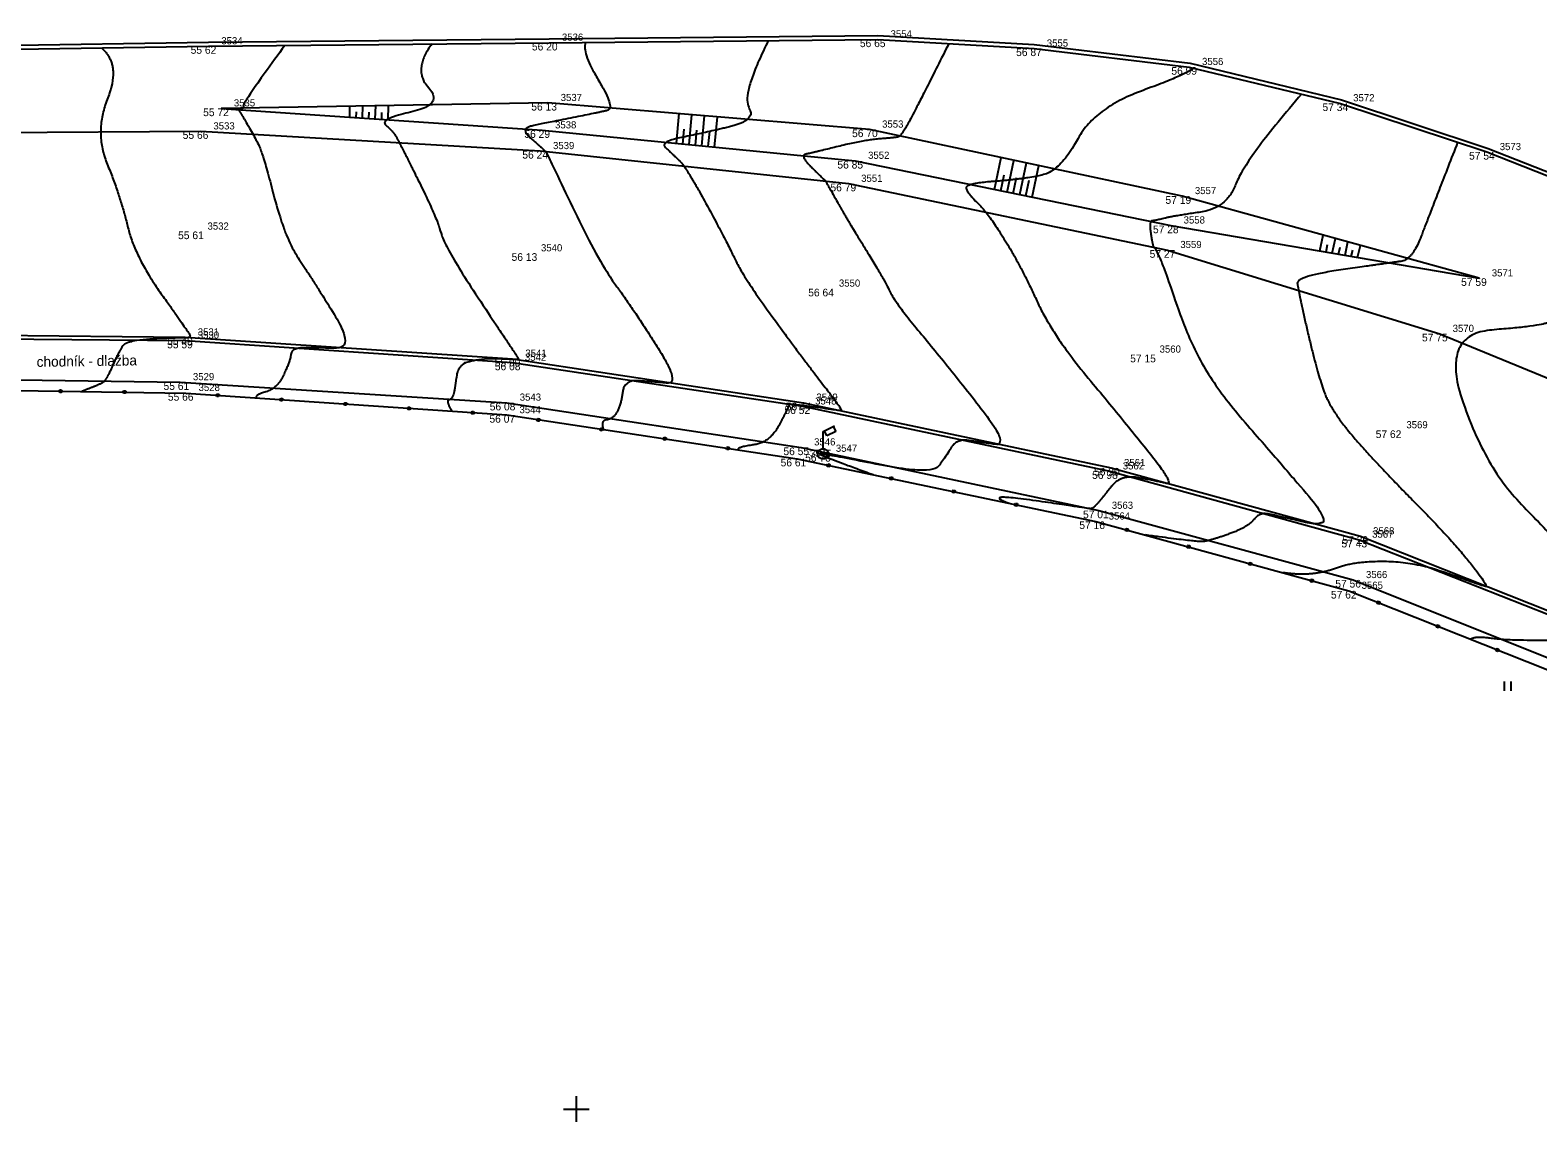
# Model space of a CAD drawing. Extents: x -704017 to -701500, y -1008977 to -1008450.
# Drawn here: x -702071.4 to -702012.4, y -1008850.5 to -1008807.8 of the extents above; entities that cross this region are included whole.
import ezdxf

# ---------------------------------------------------------------- set-up
doc = ezdxf.new("R2010")
doc.units = 0
for name, color, linetype in [('Z_body', 7, 'Continuous'), ('Z_body_cisla', 7, 'Continuous'), ('Z_body_vysky', 7, 'Continuous'), ('Z_chodnik', 7, 'Continuous'), ('Z_hekt_sit', 7, 'Continuous'), ('Z_komunikace', 7, 'Continuous'), ('Z_obruby', 7, 'Continuous'), ('Z_oploceni', 7, 'Continuous'), ('Z_popis', 7, 'Continuous'), ('Z_site_znaky_VO', 7, 'Continuous'), ('Z_teren_hrany_paty', 7, 'Continuous'), ('Z_vrstevnice_hlavni', 7, 'Continuous'), ('Z_vrstevnice_vedlejsi', 7, 'Continuous'), ('Z_zabradli', 7, 'Continuous')]:
    doc.layers.add(name, color=color, linetype=linetype)

# ---------------------------------------------------------------- blocks, each defined once
blk = doc.blocks.new('POINT_DISPLAY')
blk.add_line((0, 0), (0, 0))
blk = doc.blocks.new('Z530')
for p, q in [((-0.05, 0.03), (-0.03, 0.05)), ((-0.05, -0.03), (-0.05, 0.03)), ((-0.03, 0.05), (0.03, 0.05)), ((-0.03, -0.03), (-0.03, 0.03)), ((-0.03, 0.03), (0.03, 0.03)), ((-0.03, -0.03), (0.03, 0.03)), ((0.03, 0.05), (0.05, 0.03)), ((0.03, 0.03), (0.03, -0.03)), ((0.05, 0.03), (0.05, -0.03)), ((-0.03, -0.05), (-0.05, -0.03)), ((0.03, -0.03), (-0.03, -0.03)), ((0.03, -0.05), (-0.03, -0.05)), ((0.05, -0.03), (0.03, -0.05))]:
    blk.add_line(p, q)
blk = doc.blocks.new('Z306')
for p, q in [((-0.13, 0.17), (-0.13, -0.2)), ((0.13, 0.17), (0.13, -0.2))]:
    blk.add_line(p, q)
blk = doc.blocks.new('Z13')
for p, q in [((0, 0.88), (0.45, 1.1)), ((0, 0.2), (0, 0.88)), ((0.15, 0.7), (0.05, 0.9)), ((0.5, 0.88), (0.15, 0.7)), ((0.4, 1.07), (0.5, 0.88)), ((-0.2, 0.05), (-0.15, 0.15)), ((-0.2, -0.05), (-0.2, 0.05)), ((-0.15, 0.15), (-0.05, 0.2)), ((-0.05, 0.2), (0.05, 0.2)), ((0.05, 0.2), (0.15, 0.15)), ((0.15, 0.15), (0.2, 0.05)), ((0.2, 0.05), (0.2, -0.05)), ((-0.15, -0.15), (-0.2, -0.05)), ((-0.05, -0.2), (-0.15, -0.15)), ((0.05, -0.2), (-0.05, -0.2)), ((0.15, -0.15), (0.05, -0.2)), ((0.2, -0.05), (0.15, -0.15))]:
    blk.add_line(p, q)

msp = doc.modelspace()

# ---------------------------------------------------------------- linework, layer by layer
at = {"layer": 'Z_chodnik'}
for p, q in [((-702073.95, -1008821.44), (-702065.49, -1008821.57)), ((-702065.49, -1008821.57), (-702052.71, -1008822.37)), ((-702052.71, -1008822.37), (-702041.2, -1008824.12)), ((-702041.2, -1008824.12), (-702029.56, -1008826.59)), ((-702029.56, -1008826.59), (-702019.62, -1008829.3)), ((-702019.62, -1008829.3), (-702008.73, -1008833.67))]:
    msp.add_line(p, q, dxfattribs=at)
at = {"layer": 'Z_hekt_sit'}
for p, q in [((-702050, -1008849.5), (-702050, -1008850.5)), ((-702050.5, -1008850), (-702049.5, -1008850))]:
    msp.add_line(p, q, dxfattribs=at)
at = {"layer": 'Z_komunikace'}
for p, q in [((-702080.32, -1008811.84), (-702064.69, -1008811.75)), ((-702064.69, -1008811.75), (-702051.41, -1008812.52)), ((-702051.41, -1008812.52), (-702039.36, -1008813.8)), ((-702039.36, -1008813.8), (-702026.88, -1008816.4)), ((-702026.88, -1008816.4), (-702016.23, -1008819.67)), ((-702074.49, -1008819.71), (-702065.3, -1008819.81)), ((-702065.3, -1008819.81), (-702052.49, -1008820.65)), ((-702016.23, -1008819.67), (-702005.37, -1008824.15)), ((-702052.49, -1008820.65), (-702041.11, -1008822.37)), ((-702041.11, -1008822.37), (-702029.08, -1008824.92)), ((-702029.08, -1008824.92), (-702019.34, -1008827.59)), ((-702019.34, -1008827.59), (-702008.04, -1008832.07))]:
    msp.add_line(p, q, dxfattribs=at)
at = {"layer": 'Z_obruby'}
for p, q in [((-702074.45, -1008819.86), (-702065.3, -1008819.94)), ((-702065.3, -1008819.94), (-702052.51, -1008820.8)), ((-702052.51, -1008820.8), (-702041.16, -1008822.51)), ((-702041.16, -1008822.51), (-702029.13, -1008825.05)), ((-702029.13, -1008825.05), (-702019.38, -1008827.73)), ((-702019.38, -1008827.73), (-702008.12, -1008832.18))]:
    msp.add_line(p, q, dxfattribs=at)
at = {"layer": 'Z_oploceni'}
for p, q in [((-702080.8, -1008808.52), (-702064.38, -1008808.27)), ((-702064.38, -1008808.27), (-702051.06, -1008808.14)), ((-702064.38, -1008808.42), (-702051.06, -1008808.29)), ((-702051.06, -1008808.14), (-702038.21, -1008808.01)), ((-702051.06, -1008808.29), (-702038.21, -1008808.16)), ((-702038.21, -1008808.01), (-702032.09, -1008808.36)), ((-702038.21, -1008808.16), (-702032.1, -1008808.51)), ((-702080.8, -1008808.67), (-702064.38, -1008808.42)), ((-702032.1, -1008808.51), (-702026.03, -1008809.24)), ((-702032.09, -1008808.36), (-702026, -1008809.09)), ((-702026.03, -1008809.24), (-702020.12, -1008810.66)), ((-702026, -1008809.09), (-702020.08, -1008810.52)), ((-702020.12, -1008810.66), (-702014.39, -1008812.56)), ((-702020.08, -1008810.52), (-702014.34, -1008812.42)), ((-702014.34, -1008812.42), (-702010.8, -1008813.82)), ((-702014.39, -1008812.56), (-702010.86, -1008813.96))]:
    msp.add_line(p, q, dxfattribs=at)
at = {"layer": 'Z_teren_hrany_paty'}
for p, q in [((-702051.11, -1008810.64), (-702063.89, -1008810.86)), ((-702038.54, -1008811.68), (-702051.11, -1008810.64)), ((-702063.89, -1008810.86), (-702051.33, -1008811.71)), ((-702058.86, -1008811.2), (-702058.85, -1008810.77)), ((-702058.61, -1008811.22), (-702058.6, -1008810.99)), ((-702058.36, -1008811.23), (-702058.34, -1008810.76)), ((-702058.11, -1008811.25), (-702058.1, -1008811.01)), ((-702057.86, -1008811.27), (-702057.84, -1008810.76)), ((-702057.61, -1008811.29), (-702057.6, -1008811.02)), ((-702057.36, -1008811.3), (-702057.34, -1008810.75)), ((-702046.08, -1008812.22), (-702045.98, -1008811.06)), ((-702045.58, -1008812.27), (-702045.48, -1008811.11)), ((-702045.09, -1008812.32), (-702044.98, -1008811.15)), ((-702044.59, -1008812.37), (-702044.48, -1008811.19)), ((-702051.33, -1008811.71), (-702039.09, -1008812.91)), ((-702045.83, -1008812.25), (-702045.78, -1008811.67)), ((-702045.34, -1008812.3), (-702045.28, -1008811.71)), ((-702044.84, -1008812.35), (-702044.78, -1008811.76)), ((-702026.31, -1008814.29), (-702038.54, -1008811.68)), ((-702039.09, -1008812.91), (-702026.75, -1008815.44)), ((-702033.64, -1008814.03), (-702033.38, -1008812.78)), ((-702033.15, -1008814.13), (-702032.89, -1008812.89)), ((-702032.66, -1008814.23), (-702032.4, -1008812.99)), ((-702033.4, -1008814.08), (-702033.27, -1008813.46)), ((-702032.91, -1008814.18), (-702032.78, -1008813.56)), ((-702032.17, -1008814.33), (-702031.91, -1008813.09)), ((-702032.42, -1008814.28), (-702032.29, -1008813.66)), ((-702014.7, -1008817.5), (-702026.31, -1008814.29)), ((-702026.75, -1008815.44), (-702014.7, -1008817.5)), ((-702020.93, -1008816.43), (-702020.79, -1008815.82)), ((-702020.44, -1008816.52), (-702020.31, -1008815.95)), ((-702020.68, -1008816.48), (-702020.62, -1008816.18)), ((-702020.19, -1008816.56), (-702020.13, -1008816.29)), ((-702019.94, -1008816.6), (-702019.83, -1008816.08)), ((-702019.7, -1008816.65), (-702019.64, -1008816.4)), ((-702019.45, -1008816.69), (-702019.34, -1008816.22))]:
    msp.add_line(p, q, dxfattribs=at)
at = {"layer": 'Z_vrstevnice_hlavni'}
for points in [[(-702055.653, -1008808.335), (-702056.406, -1008809.361), (-702055.162, -1008810.71), (-702057.72, -1008811.278), (-702057.17, -1008811.754), (-702056.905, -1008812.201), (-702055.423, -1008815.201), (-702055.14, -1008816.307), (-702052.446, -1008820.355), (-702052.237, -1008820.688), (-702052.276, -1008820.685), (-702052.492, -1008820.667), (-702054.598, -1008820.66), (-702054.766, -1008821.973), (-702054.885, -1008822.234), (-702055.102, -1008822.298), (-702054.863, -1008822.703)], [(-702025.861, -1008809.281), (-702026.044, -1008809.493), (-702029.748, -1008810.858), (-702031.052, -1008813.278), (-702032.442, -1008813.625), (-702034.785, -1008813.793), (-702034.729, -1008814.156), (-702033.9, -1008814.938), (-702032.601, -1008817.047), (-702031.378, -1008819.731), (-702028.524, -1008823.148), (-702026.583, -1008825.605), (-702027.25, -1008825.45), (-702028.697, -1008825.169), (-702029.417, -1008826.077), (-702029.813, -1008826.536), (-702030.029, -1008826.493), (-702034.173, -1008825.898), (-702033.078, -1008826.297)]]:
    msp.add_open_spline(points, degree=2, dxfattribs=at)
at = {"layer": 'Z_vrstevnice_vedlejsi'}
for points in [[(-702049.632, -1008808.276), (-702049.808, -1008808.629), (-702048.464, -1008810.859), (-702049.107, -1008811.018), (-702051.275, -1008811.443), (-702052.211, -1008811.65), (-702051.394, -1008812.358), (-702051.191, -1008812.543), (-702051.131, -1008812.655), (-702049.139, -1008816.847), (-702047.711, -1008818.785), (-702045.915, -1008821.644), (-702046.932, -1008821.562), (-702048.125, -1008821.461), (-702048.248, -1008822.424), (-702048.547, -1008823.003), (-702049.069, -1008823.072), (-702048.933, -1008823.42)], [(-702042.493, -1008808.203), (-702043.548, -1008810.324), (-702042.951, -1008811.315), (-702044.933, -1008811.807), (-702046.74, -1008812.16), (-702046.303, -1008812.588), (-702045.714, -1008813.125), (-702044.143, -1008816.024), (-702043.428, -1008817.528), (-702040.846, -1008821.032), (-702039.541, -1008822.703), (-702039.779, -1008822.668), (-702041.148, -1008822.475), (-702041.588, -1008822.44), (-702041.676, -1008822.432), (-702041.685, -1008822.504), (-702042.424, -1008823.934), (-702043.716, -1008824.105), (-702043.674, -1008824.212)], [(-702035.433, -1008808.319), (-702036.646, -1008810.748), (-702037.292, -1008811.946), (-702037.524, -1008812.004), (-702038.723, -1008812.09), (-702040.759, -1008812.595), (-702041.276, -1008812.696), (-702040.318, -1008813.633), (-702040.236, -1008813.707), (-702039.592, -1008814.896), (-702037.899, -1008817.646), (-702037.525, -1008818.466), (-702035.513, -1008820.876), (-702033.003, -1008824.088), (-702034.233, -1008823.909), (-702035.145, -1008823.78), (-702035.586, -1008824.553), (-702036.139, -1008825.194), (-702040.461, -1008824.337), (-702040.528, -1008824.404), (-702038.387, -1008825.184)], [(-702068.572, -1008808.484), (-702067.796, -1008809.153), (-702068.858, -1008811.774), (-702067.826, -1008814.297), (-702067.259, -1008816.658), (-702065.268, -1008819.465), (-702065.044, -1008819.827), (-702065.3, -1008819.823), (-702067.588, -1008819.92), (-702067.895, -1008820.39), (-702068.398, -1008821.525), (-702068.688, -1008821.68), (-702069.341, -1008821.929)], [(-702061.394, -1008808.391), (-702063.088, -1008810.699), (-702062.955, -1008810.844), (-702063.229, -1008810.905), (-702063.17, -1008810.956), (-702062.629, -1008811.869), (-702062.237, -1008812.663), (-702061.409, -1008815.899), (-702060.341, -1008817.505), (-702058.639, -1008820.247), (-702060.176, -1008820.224), (-702061.124, -1008820.221), (-702061.189, -1008820.733), (-702061.683, -1008821.808), (-702062.579, -1008822.071), (-702062.515, -1008822.179)], [(-702021.64, -1008810.295), (-702023.834, -1008812.838), (-702024.569, -1008814.772), (-702026.603, -1008815.057), (-702027.36, -1008815.246), (-702027.611, -1008815.263), (-702027.461, -1008816.234), (-702027.4, -1008816.292), (-702027.304, -1008816.448), (-702027.015, -1008817.082), (-702025.637, -1008821.12), (-702021.726, -1008825.561), (-702020.339, -1008827.316), (-702022.674, -1008826.776), (-702023.28, -1008826.658), (-702023.743, -1008827.241), (-702025.223, -1008827.773), (-702025.716, -1008827.825), (-702027.745, -1008827.542)], [(-702015.536, -1008812.18), (-702016.651, -1008815.038), (-702017.312, -1008816.778), (-702018.198, -1008816.902), (-702021.826, -1008817.42), (-702021.777, -1008817.967), (-702021.071, -1008821.033), (-702020.504, -1008822.694), (-702018.513, -1008824.955), (-702015.773, -1008827.721), (-702014.291, -1008829.592), (-702014.628, -1008829.518), (-702017.191, -1008828.595), (-702019.509, -1008828.575), (-702020.704, -1008829.004), (-702021.712, -1008829.112), (-702022.37, -1008829.02)], [(-702006.569, -1008816.203), (-702008.504, -1008816.782), (-702011.42, -1008818.925), (-702012.081, -1008819.367), (-702016.23, -1008819.67), (-702014.467, -1008824.909), (-702011.526, -1008827.876), (-702008.28, -1008831.975), (-702009.018, -1008831.813), (-702009.371, -1008831.686), (-702010.12, -1008831.679), (-702013.708, -1008831.672), (-702014.832, -1008831.496), (-702015.028, -1008831.624)]]:
    msp.add_open_spline(points, degree=2, dxfattribs=at)
at = {"layer": 'Z_zabradli'}
for p, q in [((-702073.92, -1008821.86), (-702065.27, -1008821.99)), ((-702065.27, -1008821.99), (-702052.72, -1008822.85)), ((-702052.72, -1008822.85), (-702041.36, -1008824.56)), ((-702041.36, -1008824.56), (-702029.68, -1008827.01)), ((-702029.68, -1008827.01), (-702019.79, -1008829.73)), ((-702019.79, -1008829.73), (-702008.8, -1008834.1))]:
    msp.add_line(p, q, dxfattribs=at)

# ---------------------------------------------------------------- block references
at = {"layer": 'Z_body'}
for p in [(-702051.06, -1008808.29), (-702038.21, -1008808.16), (-702064.38, -1008808.42), (-702032.1, -1008808.51), (-702026.03, -1008809.24), (-702051.11, -1008810.64), (-702020.12, -1008810.66), (-702063.89, -1008810.86), (-702064.69, -1008811.75), (-702051.33, -1008811.71), (-702038.54, -1008811.68), (-702051.41, -1008812.52), (-702039.09, -1008812.91), (-702014.39, -1008812.56), (-702039.36, -1008813.8), (-702026.31, -1008814.29), (-702064.92, -1008815.67), (-702026.75, -1008815.44), (-702051.88, -1008816.52), (-702026.88, -1008816.4), (-702014.7, -1008817.5), (-702040.23, -1008817.91), (-702065.3, -1008819.81), (-702065.3, -1008819.94), (-702016.23, -1008819.67), (-702052.49, -1008820.65), (-702027.69, -1008820.49), (-702052.51, -1008820.8), (-702065.49, -1008821.57), (-702065.27, -1008821.99), (-702052.71, -1008822.37), (-702041.11, -1008822.37), (-702052.72, -1008822.85), (-702041.16, -1008822.51), (-702018.04, -1008823.45), (-702041.2, -1008824.12), (-702041.36, -1008824.56), (-702040.35, -1008824.37), (-702029.13, -1008825.05), (-702029.08, -1008824.92), (-702029.56, -1008826.59), (-702029.68, -1008827.01), (-702019.38, -1008827.73), (-702019.34, -1008827.59), (-702019.62, -1008829.3), (-702019.79, -1008829.73)]:
    msp.add_blockref('POINT_DISPLAY', p, dxfattribs=at)
at = {"layer": 'Z_popis'}
msp.add_blockref('Z306', (-702013.59, -1008833.44), dxfattribs=at)
at = {"layer": 'Z_site_znaky_VO'}
msp.add_blockref('Z13', (-702040.35, -1008824.37), dxfattribs=at)
at = {"layer": 'Z_zabradli'}
for p, rotation in [((-702070.17, -1008821.92), 179.1), ((-702067.67, -1008821.95), 179.1), ((-702064.02, -1008822.08), 176.1), ((-702061.53, -1008822.25), 176.1), ((-702059.03, -1008822.42), 176.1), ((-702056.54, -1008822.59), 176.1), ((-702054.05, -1008822.76), 176.1), ((-702051.48, -1008823.04), 171.4), ((-702049.01, -1008823.41), 171.4), ((-702046.54, -1008823.78), 171.4), ((-702044.07, -1008824.15), 171.4), ((-702040.14, -1008824.82), 168.2), ((-702037.69, -1008825.33), 168.2), ((-702035.24, -1008825.84), 168.2), ((-702032.8, -1008826.36), 168.2), ((-702028.47, -1008827.34), 164.6), ((-702026.06, -1008828), 164.6), ((-702023.65, -1008828.67), 164.6), ((-702021.24, -1008829.33), 164.6), ((-702018.63, -1008830.19), -21.699999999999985), ((-702016.31, -1008831.12), -21.699999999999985), ((-702013.98, -1008832.04), -21.699999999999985)]:
    msp.add_blockref('Z530', p, dxfattribs=dict(at, rotation=rotation))

# ---------------------------------------------------------------- texts
at = {"layer": 'Z_body_cisla'}
for s, p in [('3534', (-702063.88, -1008808.35)), ('3536', (-702050.56, -1008808.21)), ('3554', (-702037.71, -1008808.08)), ('3555', (-702031.6, -1008808.44)), ('3556', (-702025.53, -1008809.16)), ('3535', (-702063.39, -1008810.78)), ('3537', (-702050.61, -1008810.57)), ('3572', (-702019.62, -1008810.58)), ('3533', (-702064.19, -1008811.68)), ('3538', (-702050.83, -1008811.64)), ('3553', (-702038.04, -1008811.61)), ('3539', (-702050.91, -1008812.45)), ('3573', (-702013.89, -1008812.49)), ('3552', (-702038.59, -1008812.83)), ('3551', (-702038.86, -1008813.73)), ('3557', (-702025.81, -1008814.21)), ('3532', (-702064.42, -1008815.6)), ('3558', (-702026.25, -1008815.36)), ('3540', (-702051.38, -1008816.45)), ('3559', (-702026.38, -1008816.32)), ('3571', (-702014.2, -1008817.43)), ('3550', (-702039.73, -1008817.83)), ('3531', (-702064.8, -1008819.74)), ('3570', (-702015.73, -1008819.6)), ('3530', (-702064.8, -1008819.86)), ('3560', (-702027.19, -1008820.41)), ('3542', (-702052.01, -1008820.73)), ('3541', (-702051.99, -1008820.57)), ('3529', (-702064.99, -1008821.49)), ('3528', (-702064.77, -1008821.91)), ('3544', (-702052.22, -1008822.78)), ('3543', (-702052.21, -1008822.29)), ('3548', (-702040.66, -1008822.44)), ('3549', (-702040.61, -1008822.29)), ('3569', (-702017.54, -1008823.37)), ('3545', (-702040.86, -1008824.49)), ('3546', (-702040.7, -1008824.04)), ('3547', (-702039.85, -1008824.29)), ('3562', (-702028.63, -1008824.98)), ('3561', (-702028.58, -1008824.85)), ('3563', (-702029.06, -1008826.52)), ('3564', (-702029.18, -1008826.94)), ('3567', (-702018.88, -1008827.65)), ('3568', (-702018.84, -1008827.52)), ('3566', (-702019.12, -1008829.23)), ('3565', (-702019.29, -1008829.65))]:
    msp.add_text(s, height=0.28, dxfattribs=at).set_placement(p)
at = {"layer": 'Z_body_vysky'}
for s, p in [('56 20', (-702051.735, -1008808.59)), ('56 65', (-702038.91, -1008808.46)), ('55 62', (-702065.08, -1008808.72)), ('56 87', (-702032.8, -1008808.81)), ('56 99', (-702026.73, -1008809.54)), ('56 13', (-702051.76, -1008810.94)), ('57 34', (-702020.82, -1008810.96)), ('55 72', (-702064.59, -1008811.16)), ('55 66', (-702065.39, -1008812.05)), ('56 29', (-702052.03, -1008812.01)), ('56 70', (-702039.215, -1008811.98)), ('56 24', (-702052.11, -1008812.82)), ('56 85', (-702039.79, -1008813.21)), ('57 54', (-702015.09, -1008812.86)), ('56 79', (-702040.06, -1008814.1)), ('57 19', (-702026.96, -1008814.59)), ('55 61', (-702065.57, -1008815.97)), ('57 28', (-702027.45, -1008815.74)), ('56 13', (-702052.53, -1008816.82)), ('57 27', (-702027.58, -1008816.7)), ('57 59', (-702015.4, -1008817.8)), ('56 64', (-702040.93, -1008818.21)), ('55 49', (-702066, -1008820.11)), ('55 59', (-702066, -1008820.24)), ('57 75', (-702016.93, -1008819.97)), ('55 99', (-702053.19, -1008820.95)), ('57 15', (-702028.34, -1008820.79)), ('56 08', (-702053.185, -1008821.1)), ('55 61', (-702066.14, -1008821.87)), ('55 66', (-702065.97, -1008822.29)), ('56 08', (-702053.385, -1008822.67)), ('56 44', (-702041.81, -1008822.67)), ('56 07', (-702053.395, -1008823.15)), ('56 52', (-702041.86, -1008822.81)), ('57 62', (-702018.74, -1008823.75)), ('56 55', (-702041.9, -1008824.42)), ('56 61', (-702042.01, -1008824.86)), ('56 78', (-702041.05, -1008824.67)), ('56 98', (-702029.83, -1008825.35)), ('56 90', (-702029.755, -1008825.22)), ('57 01', (-702030.185, -1008826.89)), ('57 16', (-702030.33, -1008827.31)), ('57 43', (-702020.08, -1008828.03)), ('57 29', (-702020.04, -1008827.89)), ('57 56', (-702020.32, -1008829.6)), ('57 62', (-702020.49, -1008830.03))]:
    msp.add_text(s, height=0.3, dxfattribs=at).set_placement(p)
at = {"layer": 'Z_popis'}
msp.add_text('chodník - dlažba', height=0.4, rotation=0.9, dxfattribs=at).set_placement((-702071.1, -1008820.97))

doc.saveas('drawing.dxf')
